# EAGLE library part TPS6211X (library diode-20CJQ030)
Ti's TPS6211* 17-V, 1.5-A, SYNCHRONOUS STEP-DOWN CONVERTER Description: The TPS6211x devices are a family of low-noise synchronous step-down dc-dc converters that are ideally suited for systems powered from a 2-cell Li-ion battery or from a 12-V or 15-V rail. The TPS6211x is a synchronous PWM converter with integrated ? and P-channel power MOSFET switches. Synchronous rectification is used to increase efficiency and to reduce external component count. To achieve highest efficiency over a wide load current range, the converter enters a power-saving, pulse-frequency modulation (PFM) mode at light load currents. Operating frequency is typically 1 MHz, allowing the use of small inductor and capacitor values. The device can be syncronized to an external clock signal in the range of 0.8 MHz to 1.4 MHz. For low noise operation, the converter can be operated in PWM-only mode. In the shutdown mode, the current consumption is reduced to less than 2 ?A. The TPS6211x is available in the 16-pin (RSA) QFN package, and operates over a free-air temperature range of ?40°C to 85°C. Features: High-Efficiency Synchronous Step-DownConverter With up to 95% Efficiency 3.1-V to 17-V Operating Input Voltage Range Adjustable Output Voltage Range From 1.2 V to 16 V Fixed Output Voltage Options Available in 3.3 V and 5 V Synchronizable to External Clock Signal up to 1.4 MHz Up to 1.5-A Output Current High Efficiency Over a Wide Load Current Range Due to PFM/PWM Operation Mode 100% Maximum Duty Cycle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
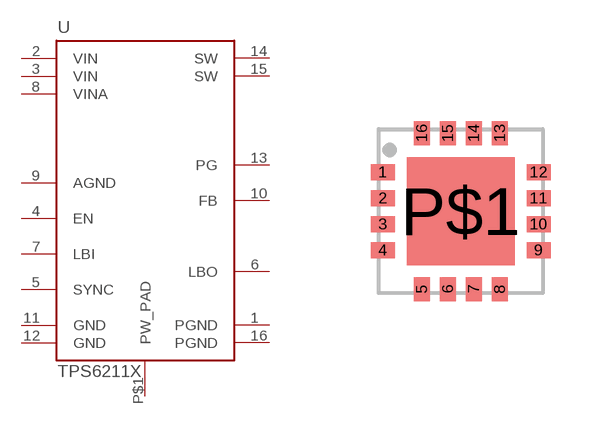
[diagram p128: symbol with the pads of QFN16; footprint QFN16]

Designator prefix U

## TPS6211X-RSA  [QFN16]
1  PGND  pwr
2  VIN  pwr
3  VIN  pwr
4  EN  in
5  SYNC  in
6  LBO  pas
7  LBI  pas
8  VINA  pwr
9  AGND  pwr
10  FB  pas
11  GND  pwr
12  GND  pwr
13  PG  pas
14  SW  pas
15  SW  pas
16  PGND  pwr
P$1  PW_PAD  pwr

## Footprint QFN16 (pad centres in mm)
16pin QFN package E.g.:TPS6211*
smd 0.6 x 0.4: 1 -1.95,0.975; 2 -1.95,0.325; 3 -1.95,-0.325; 4 -1.95,-0.975; 9 1.95,-0.975; 10 1.95,-0.325; 11 1.95,0.325; 12 1.95,0.975
smd 0.4 x 0.6: 5 -0.975,-1.95; 6 -0.325,-1.95; 7 0.325,-1.95; 8 0.975,-1.95; 13 0.975,1.95; 14 0.325,1.95; 15 -0.325,1.95; 16 -0.975,1.95
smd 2.7 x 2.7: P$1 0,0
